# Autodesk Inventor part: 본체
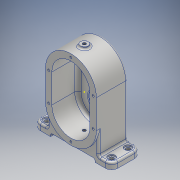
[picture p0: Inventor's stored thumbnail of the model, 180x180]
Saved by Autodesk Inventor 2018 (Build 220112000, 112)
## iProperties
Created: 2021-05
Part Number: 본체
Material: 알루미늄 6061
Document SubType Name: Modeling
Designer: Admin
Density: 2.7 g/cm^3
Appearance: 알루미늄 - 평지
Mass: 756.778 g
Surface Area: 582.071 cm^2
Volume: 280.288 cm^3
Author: Admin
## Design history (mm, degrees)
sketch "스케치1"
  geometry: L1 (56, 0)-(-56, 0) reference; L2 (0, -87.5)-(0, 87.5) reference; L3 (0, 22.5)-(0, -22.5); L4 (40, 22.5)-(40, -22.5); L5 (-40, -22.5)-(-40, 22.5); A1 r 40 centre (0, 22.5) between (40, 22.5) and (-40, 22.5); A2 r 40 centre (0, -22.5) between (-40, -22.5) and (40, -22.5); 2 further points
  constraints: 8 end point, 4 point on circle, 4 tangent, 2 centre point, 2 point on line, 1 midpoint, 1 parallel, 1 symmetric about line
  dimensions: "d0" = 80 distance between parallel lines of L5 L4; "d1" = 45 distance of L3.end L3.start
extrude "돌출1" new body sketch "스케치1" distance "d2" = 28; taper "d4" = 0 deg; dims "d3" = 21, "d5" = 0
sketch "스케치2"
  geometry: 1 further point
node "작업 평면1"
sketch "스케치3"
  geometry: L1 (40, 28)-(40, -21) reference; L2 (-40, 28)-(40, 28) reference; L3 (-40, -21)-(-40, 28) reference; L4 (40, -21)-(-40, -21) reference; L5 (-56, 0)-(56, 0) reference; L6 (0, -30.8)-(0, 37.8) reference; L7 (-61, -18)-(61, -18); L8 (61, -18)-(61, 28); L9 (61, 28)-(-61, 28); L10 (-61, 28)-(-61, -18); L11 (-61, -18)-(61, 28); L12 (61, -18)-(-61, 28); 2 further points
  constraints: 12 end point, 2 midpoint, 2 parallel, 1 horizontal, 1 perpendicular, 1 point on line
  dimensions: "d7" = 122 distance between parallel lines of L8 L10; "d8" = 3 distance between parallel lines of L4 L7; "d9" = 46 distance between parallel lines of L7 L9
extrude "돌출2" join sketch "스케치3" distance "d10" = 10; taper "d11" = 0 deg
sketch "스케치4"
  geometry: L1 (40, 28)-(40, -21) reference; L2 (-40, 28)-(40, 28) reference; L3 (-40, -21)-(-40, 28) reference; L4 (40, -21)-(-40, -21) reference; L5 (-61, -18)-(61, -18) reference; L6 (-40, 28)-(40, 28); L7 (40, 28)-(40, -18); L8 (40, -18)-(-40, -18); L9 (-40, -18)-(-40, 28); 1 further point
  constraints: 8 end point, 2 parallel, 2 point on line, 1 horizontal, 1 perpendicular
extrude "돌출3" join sketch "스케치4" distance "d12" = 50; taper "d13" = 0 deg
sketch "스케치5"
  geometry: L1 (61, 59.5)-(40, 59.5) reference; L2 (61, 69.5)-(61, 59.5) reference; L3 (61, 69.5)-(-61, 69.5) reference; L4 (-61, 69.5)-(-61, 59.5) reference; L5 (-40, 59.5)-(-61, 59.5) reference; L6 (-40, 59.5)-(-40, -22.5) reference; L7 (40, -22.5)-(40, 59.5) reference; L8 (-85.4, 0)-(85.4, 0) reference; L9 (0, 95.9)-(0, -88.9) reference; L10 (0, -22.5)-(0, 22.5); L11 (26, -22.5)-(26, 22.5); L12 (-26, 22.5)-(-26, -22.5); A1 r 40 centre (0, -22.5) between (-40, -22.5) and (40, -22.5) reference; A2 r 26 centre (0, -22.5) between (-26, -22.5) and (26, -22.5); A3 r 26 centre (0, 22.5) between (26, 22.5) and (-26, 22.5); 2 further points
  constraints: 8 end point, 4 point on circle, 4 tangent, 2 centre point, 1 midpoint, 1 parallel, 1 point on line, 1 symmetric about line
  dimensions: "d14" = 52 distance between parallel lines of L12 L11
extrude "돌출4" join sketch "스케치5" distance "d15" = 11; taper "d16" = 0 deg
sketch "스케치6"
  geometry: L1 (-85.4, 0)-(85.4, 0) reference; L2 (0, 95.9)-(0, -88.9) reference; L3 (26, -22.5)-(26, 22.5) reference; L4 (-26, 22.5)-(-26, -22.5) reference; L5 (26, 7.5)-(22, 7.5); L6 (22, 7.5)-(-26, 7.5); L7 (26, 22.5)-(26, -22.5) reference; L8 (26, -22.5)-(26, 7.5); L9 (-26, -22.5)-(-26, 7.5); A1 r 26 centre (0, 22.5) between (26, 22.5) and (-26, 22.5) reference; A2 r 26 centre (0, -22.5) between (-26, -22.5) and (26, -22.5) reference; A3 r 26 centre (0, -22.5) between (-26, -22.5) and (26, -22.5); 1 further point
  constraints: 8 end point, 3 point on line, 2 collinear, 2 point on circle, 1 centre point, 1 coincident, 1 perpendicular
  dimensions: "d17" = 30 distance from line of L6 A2.centre
extrude "돌출5" cut sketch "스케치6" distance "d18" = 3; taper "d19" = 0 deg
node "작업 평면2"
sketch "스케치8"
  geometry: L1 (0, -33)-(0, 51) reference; L2 (-40, -21)-(40, -21) reference; C1 r 6 at (0, 0); 1 further point
  constraints: 1 centre point, 1 point on line
  dimensions: "d21" = 21 distance from line of L2 C1.centre; "d22" = 12 diameter of C1
extrude "돌출6" join sketch "스케치8" distance "d23" = 10; taper "d24" = 0 deg
sketch "스케치9"
  geometry: L1 (-40, 22.5)-(-40, -22.5) reference; L2 (40, -22.5)-(40, 22.5) reference; L3 (0, -96.5)-(0, 92.5) reference; L4 (-85.4, 0)-(85.4, 0) reference; L5 (0, 22.5)-(0, -22.5); L6 (-30, 22.5)-(-30, -22.5); L7 (30, -22.5)-(30, 22.5); A1 r 40 centre (0, -22.5) between (-40, -22.5) and (40, -22.5) reference; A2 r 40 centre (0, 22.5) between (40, 22.5) and (-40, 22.5) reference; A3 r 30 centre (0, 22.5) between (30, 22.5) and (-30, 22.5); A4 r 30 centre (0, -22.5) between (-30, -22.5) and (30, -22.5); 2 further points
  constraints: 8 end point, 4 point on circle, 4 tangent, 2 centre point, 1 collinear, 1 midpoint, 1 parallel
  dimensions: "d25" = 60 distance between parallel lines of L7 L6
extrude "돌출7" cut sketch "스케치9" distance "d26" = 41; taper "d27" = 0 deg
sketch "스케치10"
  geometry: L1 (-30, -22.5)-(-30, 22.5) reference; L2 (30, 22.5)-(30, -22.5) reference; C1 r 14 at (0, 22.5); C2 r 14 at (0, -22.5); A1 r 30 centre (0, -22.5) between (-30, -22.5) and (30, -22.5) reference; A2 r 30 centre (0, 22.5) between (30, 22.5) and (-30, 22.5) reference; 1 further point
  constraints: 2 centre point, 2 coincident
  dimensions: "d28" = 28 diameter of C1; "d29" = 28 diameter of C2 (= d28)
extrude "돌출8" cut sketch "스케치10" distance "d30" = 8; taper "d31" = 0 deg
sketch "스케치11"
  geometry: L1 (26, 7.5)-(26, -22.5) reference; L2 (-26, 7.5)-(26, 7.5) reference; L3 (-26, -22.5)-(-26, 7.5) reference; C1 r 14 at (0, -22.5); A1 r 26 centre (0, -22.5) between (-26, -22.5) and (26, -22.5) reference; 1 further point
  constraints: 1 centre point, 1 coincident
  dimensions: "d32" = 28 diameter of C1
extrude "돌출9" cut sketch "스케치11" distance "d33" = 4; taper "d34" = 0 deg
sketch "스케치12"
  geometry: C1 r 14 at (0, 0) reference; C2 r 11 at (0, 0); 1 further point
  constraints: 1 centre point, 1 coincident
  dimensions: "d35" = 22 diameter of C2
extrude "돌출10" cut sketch "스케치12" extent not by distance; stored distance "d36" = 4; taper "d37" = 0 deg
sketch "스케치13"
  geometry: L1 (-30, 0)-(-30, 45) reference; L2 (30, 45)-(30, 0) reference; C1 r 14 at (0, 45) reference; C2 r 14 at (0, 0) reference; C3 r 10 at (0, 0); A1 r 30 centre (0, 0) between (-30, 0) and (30, 0) reference; A2 r 30 centre (0, 45) between (30, 45) and (-30, 45) reference; 1 further point
  constraints: 1 centre point, 1 coincident
  dimensions: "d38" = 20 diameter of C3
extrude "돌출11" cut sketch "스케치13" distance "d39" = 4; taper "d40" = 0 deg
sketch "스케치14"
  geometry: L1 (-85.4, 0)-(85.4, 0) reference; L2 (0, -96.5)-(0, 92.5) reference; L3 (-30, -22.5)-(-30, 22.5) reference; L4 (30, 22.5)-(30, -22.5) reference; L5 (-40, 22.5)-(-40, -22.5) reference; L6 (40, -22.5)-(40, 22.5) reference; A1 r 30 centre (0, -22.5) between (-30, -22.5) and (30, -22.5) reference; A2 r 30 centre (0, 22.5) between (30, 22.5) and (-30, 22.5) reference; A3 r 40 centre (0, -22.5) between (-40, -22.5) and (40, -22.5) reference; A4 r 40 centre (0, 22.5) between (40, 22.5) and (-40, 22.5) reference; 4 further points
  constraints: 1 point on line, 1 symmetric about line
  dimensions: "d41" = 70 distance of point (35, 22.5) point (-35, 22.5); "d42" = 22.5 distance from line of L1 point (35, 22.5); "d43" = 35 horizontal distance of point (35, 22.5) point (0, 57.5)
hole "구멍1" sketch "스케치14" at (0, 57.5), (-35, 22.5), (35, 22.5) diameter "d44" = 3.242; stored, may be unused: countersink angle "d48" = 90 deg, drill point angle "d50" = 118 deg; dims "d45" = 8, "d46" = 4, "d47" = 2, "d49" = 10
sketch "스케치15"
  geometry: L1 (-85.4, 0)-(85.4, 0) reference; L2 (0, 96.5)-(0, -92.5) reference; L3 (26, 7.5)-(26, -22.5) reference; L4 (-26, 7.5)-(26, 7.5) reference; L5 (-26, -22.5)-(-26, 7.5) reference; C1 r 14 at (0, -22.5) reference; A1 r 26 centre (0, -22.5) between (-26, -22.5) and (26, -22.5) reference; 2 further points
  constraints: 1 point on line
  dimensions: "d51" = 20 distance of C1.centre point (0, -42.5)
hole "구멍2" sketch "스케치15" at (0, -42.5) diameter "d52" = 3.242; stored, may be unused: countersink angle "d56" = 90 deg, drill point angle "d58" = 118 deg; dims "d53" = 8, "d54" = 4, "d55" = 2, "d57" = 10
fillet "모깎기1" dims "d62" = 10
sketch "스케치16"
  geometry: L1 (51, 28)-(-51, 28) reference; L2 (61, -8)-(61, 18) reference; L3 (-51, -18)-(51, -18) reference; L4 (-61, 18)-(-61, -8) reference; A1 r 10 centre (-51, 18) between (-51, 28) and (-61, 18) reference; A2 r 10 centre (51, 18) between (61, 18) and (51, 28) reference; A3 r 10 centre (51, -8) between (51, -18) and (61, -8) reference; A4 r 10 centre (-51, -8) between (-61, -8) and (-51, -18) reference; 5 further points
  constraints: 4 coincident
hole "구멍3" sketch "스케치16" at (51, 18), (51, -8), (-51, -8), (-51, 18) diameter "d63" = 6.6; stored, may be unused: countersink angle "d67" = 90 deg, drill point angle "d69" = 118 deg; dims "d64" = 6, "d65" = 11, "d66" = 2, "d68" = 8
sketch "스케치17"
  geometry: 2 further points
  constraints: 1 coincident
hole "구멍4" sketch "스케치17" at (0, 0) diameter "d70" = 4.917; stored, may be unused: countersink angle "d74" = 90 deg, drill point angle "d76" = 118 deg; dims "d71" = 17, "d72" = 11, "d73" = 2, "d75" = 17.1
sketch "스케치18"
  geometry: L1 (-35, -52)-(35, -52); L2 (35, -52)-(35, -42); L3 (35, -42)-(-35, -42); L4 (-35, -42)-(-35, -52); L5 (51, -47)-(-51, -47) reference; L6 (-35, -52)-(35, -42); L7 (35, -52)-(-35, -42); 2 further points
  constraints: 12 end point, 3 midpoint, 2 parallel, 1 horizontal, 1 perpendicular
  dimensions: "d77" = 10 distance between parallel lines of L3 L1; "d78" = 70 distance between parallel lines of L2 L4
extrude "돌출12" cut sketch "스케치18" extent not by distance; stored distance "d79" = 10; taper "d80" = 0 deg
sketch "스케치19"
  geometry: C1 r 2.458 at (35, 18) reference; 2 further points
  constraints: 1 coincident
hole "구멍5" sketch "스케치19" at (35, 18) diameter "d81" = 4.917; stored, may be unused: countersink angle "d85" = 90 deg, drill point angle "d87" = 118 deg; dims "d82" = 17, "d83" = 12, "d84" = 1, "d86" = 17
fillet "모깎기2" dims "d88" = 3
chamfer "모따기1" distance "d89" = 1; stored, may be unused: second distance "d90" = 2, angle "d91" = 45 deg
fillet "모깎기3" dims "d92" = 0.3
node "작업 평면3"
sketch "스케치20"
  geometry: L1 (51, 69.5)-(35, 69.5) reference; L2 (40, -22.5)-(40, 56.5) reference; 2 further points
  constraints: 1 other
  dimensions: "d94" = 12 distance from line of L1 point (0, 57.5); "d95" = 40 distance from line of L2 point (0, 57.5)
feature "엠보싱1" sketch "스케치20" dims "d7" = 122, "d8" = 3, "d9" = 46, "d96" = 0.5, "d97" = 0
fillet "모깎기4" dims "d98" = 5
node "솔리드1"
mirror "미러1"
pattern_circular "원형 패턴1" dims angle "d60" = 360 deg
node "투영된 루프1"
node "투영된 루프2"
node "투영된 루프3"
node "투영된 루프4"
node "투영된 루프5"
node "투영된 루프6"
node "투영된 루프7"
node "투영된 루프8"
node "투영된 루프9"
node "투영된 루프10"
node "투영된 루프11"
node "투영된 루프12"
other parameters: "d6" = -69.5, "d20" = 135, "d93" = 32.75
